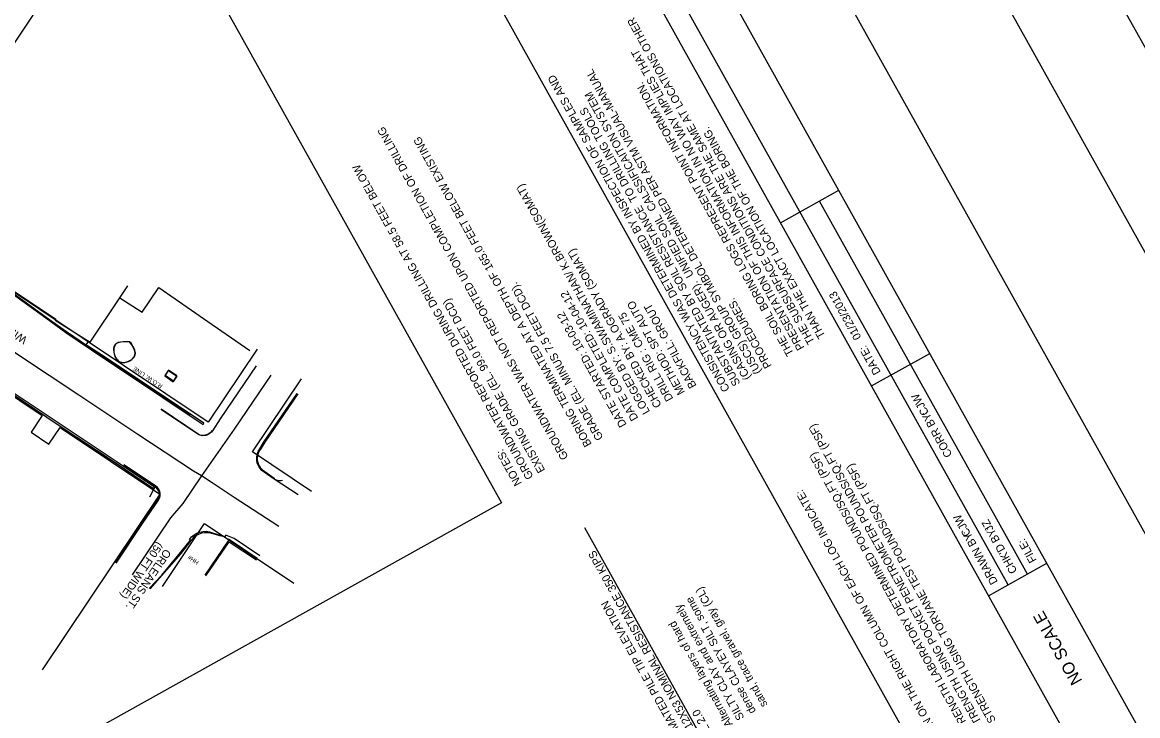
# Model space of a CAD drawing. Extents: x 13482447 to 13495412, y 324533 to 340229.
# Drawn here: x 13492545 to 13493214, y 331177 to 331592 of the extents above; entities that cross this region are included whole.
import ezdxf

# ---------------------------------------------------------------- set-up
doc = ezdxf.new("R2010")
doc.units = 0
for name, color, linetype in [('BORDER', 7, 'Continuous'), ('Default', 7, 'Continuous'), ('DETAIL_TEXT_DIMEN_PR', 7, 'Continuous'), ('Level 1', 7, 'Continuous'), ('TYPICAL_TEXT_DIMEN_PR', 7, 'Continuous'), ('V-ANNO-TEXT', 7, 'Continuous'), ('V-BLDG-OTLN', 7, 'Continuous'), ('V-PROP-RWAY', 7, 'Continuous'), ('V-PROP-RWAY-IDEN', 7, 'Continuous'), ('V-PVMT-BACK', 7, 'Continuous'), ('V-PVMT-CNTR', 7, 'Continuous'), ('V-PVMT-ROAD', 7, 'Continuous'), ('V-SITE-FENC-DEMO', 7, 'Continuous'), ('V-STRC-WALL', 7, 'Continuous'), ('V-TOPO-IDEN', 7, 'Continuous')]:
    doc.layers.add(name, color=color, linetype=linetype)

msp = doc.modelspace()

# ---------------------------------------------------------------- linework, layer by layer
at = {"layer": 'Default'}
for points in [[(13492586.34, 331745.09), (13492832.27, 331304.34)], [(13492832.27, 331304.34), (13492334.38, 331026.77)]]:
    msp.add_lwpolyline(points, dxfattribs=at)
at = {"layer": 'Level 1'}
for p, q in [((13493612.91, 330747.03), (13492913.2, 332001.03)), ((13493636.07, 330828.66), (13492994.84, 331977.87)), ((13493541.18, 330707.01), (13492841.48, 331961.01)), ((13493459.55, 330730.17), (13492818.32, 331879.38)), ((13493424.62, 330710.68), (13492783.39, 331859.89)), ((13493352.3, 330668.3), (13492709.75, 331819.87)), ((13493136.11, 331255.1), (13492824.27, 331813.99)), ((13492999.74, 331472.17), (13493034.69, 331491.66)), ((13493147.75, 331261.6), (13493023.02, 331485.15)), ((13493054.3, 331374.35), (13493089.23, 331393.84)), ((13493124.47, 331248.61), (13493159.4, 331268.1))]:
    msp.add_line(p, q, dxfattribs=at)
at = {"layer": 'TYPICAL_TEXT_DIMEN_PR'}
msp.add_line((13492981.96, 331110.55), (13492882.24, 331289.27), dxfattribs=at)
at = {"layer": 'V-BLDG-OTLN'}
for points in [[(13492472.33, 331479.25), (13492470.9, 331477.08), (13492480.41, 331470.94), (13492491.27, 331463.56), (13492512.34, 331449.48), (13492525.07, 331440.95), (13492565.12, 331414.41), (13492564.67, 331413.86), (13492585.61, 331400.62), (13492603.4, 331427.17), (13492608.29, 331434.36)], [(13492685.86, 331270.89), (13492668.78, 331282.18), (13492654.46, 331260.96)], [(13492655.05, 331260.55), (13492668.99, 331280.9), (13492685.37, 331270.16)]]:
    msp.add_lwpolyline(points, dxfattribs=at)
at = {"layer": 'V-PROP-RWAY'}
for p, q in [((13492570.67, 331625.86), (13492318.1, 331248.69)), ((13492656.37, 331352.6), (13492470.9, 331476.77)), ((13492461.91, 331420.21), (13492556.98, 331356.57)), ((13492685.74, 331396.48), (13492656.37, 331352.6)), ((13492682.96, 331334.8), (13492712.33, 331378.68)), ((13492556.98, 331356.57), (13492550.3, 331346.6)), ((13492560.94, 331339.48), (13492567.62, 331349.45)), ((13492567.62, 331349.45), (13492627.45, 331309.4)), ((13492550.3, 331346.6), (13492560.94, 331339.48)), ((13492718.45, 331311.05), (13492682.96, 331334.8)), ((13492627.45, 331309.4), (13492556.96, 331204.1)), ((13492628.98, 331254.17), (13492654.3, 331291.99)), ((13492654.3, 331291.99), (13492707.89, 331256.12))]:
    msp.add_line(p, q, dxfattribs=at)
at = {"layer": 'V-PVMT-BACK'}
for points in [[(13492710.13, 331369.7), (13492690.41, 331340.71), (13492688.14, 331337.09), (13492686.92, 331334.97), (13492686.45, 331333.96), (13492685.96, 331332.45), (13492685.76, 331330.92), (13492685.79, 331330.14), (13492685.96, 331329.08), (13492686.15, 331328.37), (13492686.7, 331327.02), (13492686.99, 331326.49), (13492687.65, 331325.5), (13492688.44, 331324.6), (13492689.04, 331324.04), (13492690.39, 331322.99), (13492696.09, 331319.02), (13492695.97, 331318.76)], [(13492601.13, 331268.22), (13492616.59, 331292.15), (13492620.02, 331297.42), (13492625.43, 331304.69), (13492626.37, 331306.1), (13492626.95, 331307.31), (13492627.22, 331308.62), (13492627.17, 331309.95), (13492626.81, 331311.24), (13492626.15, 331312.41), (13492625.24, 331313.39), (13492624.67, 331313.81)], [(13492621.56, 331307.91), (13492623.86, 331312.57), (13492624.67, 331313.81)], [(13492663.5, 331284.5), (13492662.88, 331284.67), (13492658.73, 331285.9), (13492658.01, 331286.1), (13492656.13, 331286.39), (13492654.23, 331286.36), (13492652.36, 331286.02), (13492650.57, 331285.37), (13492648.92, 331284.43), (13492647.45, 331283.22), (13492646.21, 331281.79), (13492646.15, 331281.71), (13492640.07, 331273.98), (13492621.45, 331252.64)]]:
    msp.add_lwpolyline(points, dxfattribs=at)
at = {"layer": 'V-PVMT-CNTR'}
for points in [[(13492698.81, 331290.16), (13492671.99, 331307.42), (13492658.91, 331316.29), (13492652.45, 331320.46), (13492647.72, 331323.27), (13492614.25, 331345.31), (13492578.94, 331368.92), (13492543.35, 331392.51), (13492508.4, 331416.01), (13492474.51, 331438.47), (13492456.22, 331451.24), (13492427.05, 331470.26), (13492400.48, 331488.1), (13492367.89, 331510.12), (13492333.56, 331533.05), (13492300.46, 331555.5), (13492272.59, 331574.14)], [(13492694.11, 331380.83), (13492672.13, 331348.5), (13492652.45, 331320.46), (13492641.24, 331303.81), (13492633.93, 331295.37), (13492610.86, 331261.17)]]:
    msp.add_lwpolyline(points, dxfattribs=at)
at = {"layer": 'V-PVMT-ROAD'}
for points in [[(13492603.4, 331427.17), (13492616.77, 331418.65), (13492626.79, 331433.32), (13492656.18, 331412.99), (13492681.52, 331395.55)], [(13492609.63, 331400.82), (13492606.72, 331400.89), (13492605.45, 331400.85), (13492603.78, 331400.68), (13492602.4, 331400.33), (13492601.81, 331400.08), (13492601.14, 331399.65), (13492600.85, 331399.39), (13492600.48, 331398.94), (13492600.07, 331398.13), (13492599.77, 331396.79), (13492599.72, 331396.13), (13492599.8, 331394.72), (13492599.99, 331393.64), (13492600.51, 331392.05), (13492600.86, 331391.31), (13492601.43, 331390.4), (13492601.76, 331389.99), (13492602.3, 331389.46), (13492603.22, 331388.84), (13492604.21, 331388.49), (13492604.92, 331388.38), (13492606.4, 331388.42), (13492607.16, 331388.55), (13492608.63, 331389.03), (13492609.56, 331389.47), (13492610.68, 331390.18), (13492611.17, 331390.58), (13492612.06, 331391.55), (13492612.49, 331392.32), (13492612.67, 331392.85), (13492612.79, 331393.98), (13492612.74, 331394.58), (13492612.42, 331395.86), (13492611.84, 331397.26), (13492611.32, 331398.28), (13492610.02, 331400.51)], [(13492609.48, 331400.75), (13492606.65, 331400.79), (13492605.42, 331400.75), (13492603.79, 331400.57), (13492602.44, 331400.22), (13492601.87, 331399.97), (13492601.22, 331399.55), (13492600.95, 331399.3), (13492600.59, 331398.86), (13492600.18, 331398.07), (13492599.89, 331396.73), (13492599.86, 331396.06), (13492599.95, 331394.65), (13492600.17, 331393.56), (13492600.71, 331391.98), (13492601.07, 331391.24), (13492601.66, 331390.34), (13492601.99, 331389.94), (13492602.55, 331389.41), (13492603.49, 331388.82), (13492604.45, 331388.52), (13492605.13, 331388.43), (13492606.55, 331388.51), (13492607.27, 331388.66), (13492608.68, 331389.15), (13492609.56, 331389.59), (13492610.62, 331390.3), (13492611.09, 331390.7), (13492611.93, 331391.64), (13492612.37, 331392.43), (13492612.55, 331392.98), (13492612.64, 331394.12), (13492612.57, 331394.73), (13492612.2, 331396.02), (13492611.56, 331397.43), (13492610.99, 331398.45), (13492609.56, 331400.7)], [(13492685.19, 331386.49), (13492663.66, 331354.56), (13492658.98, 331347.38), (13492658.38, 331346.63), (13492657.92, 331346.21), (13492656.9, 331345.52), (13492655.62, 331344.95), (13492654.95, 331344.74), (13492653.93, 331344.56), (13492652.84, 331344.54), (13492652.29, 331344.61), (13492651.49, 331344.82), (13492650.31, 331345.41), (13492628.12, 331360.25)], [(13492637.59, 331380.41), (13492632.67, 331383.83), (13492630.41, 331380.49), (13492635.43, 331376.91), (13492637.59, 331380.41)], [(13492635.57, 331377.18), (13492630.66, 331380.57), (13492632.65, 331383.57), (13492637.63, 331380.19), (13492635.57, 331377.18)], [(13492710.35, 331309.1), (13492695.99, 331318.51), (13492690.08, 331322.64), (13492688.68, 331323.7), (13492687.49, 331325), (13492686.56, 331326.49), (13492685.91, 331328.12), (13492685.57, 331329.85), (13492685.55, 331331.6), (13492685.85, 331333.33), (13492686.45, 331334.98), (13492686.79, 331335.63), (13492690.07, 331341.14), (13492709.84, 331369.81)], [(13492658.86, 331347.55), (13492658.03, 331346.6), (13492657.57, 331346.19), (13492656.8, 331345.68), (13492655.85, 331345.24), (13492655.35, 331345.06), (13492654.61, 331344.86), (13492653.73, 331344.7), (13492653.38, 331344.67), (13492652.65, 331344.69), (13492651.66, 331344.91), (13492651.16, 331345.1), (13492650.4, 331345.53), (13492628.2, 331360.37)], [(13492601.2, 331268.18), (13492617.04, 331291.85), (13492626.68, 331305.8), (13492627.32, 331307.06), (13492627.66, 331308.43), (13492627.68, 331309.85), (13492627.39, 331311.23), (13492626.79, 331312.51), (13492625.92, 331313.62), (13492624.91, 331314.46), (13492605.92, 331327.01)], [(13492624.34, 331314.11), (13492605.65, 331326.61)], [(13492624.34, 331314.11), (13492624.19, 331314.43), (13492605.83, 331326.87)], [(13492695.97, 331318.76), (13492697.26, 331318.11), (13492698.66, 331317.75), (13492700.1, 331317.7), (13492701.09, 331317.86)], [(13492621, 331252.88), (13492628.71, 331261.01), (13492639.78, 331274.43), (13492645.78, 331281.98), (13492645.21, 331282.4), (13492646.47, 331283.86), (13492647.96, 331285.09), (13492649.63, 331286.07), (13492651.43, 331286.75), (13492653.33, 331287.13), (13492655.26, 331287.2), (13492657.17, 331286.94), (13492658.46, 331286.58), (13492663.64, 331284.96)], [(13492687.42, 331272.6), (13492672.01, 331283), (13492667.07, 331284.85), (13492666.27, 331283.84), (13492663.5, 331284.5)], [(13492685.91, 331270.99), (13492668.69, 331282.51)]]:
    msp.add_lwpolyline(points, dxfattribs=at)
at = {"layer": 'V-SITE-FENC-DEMO'}
msp.add_lwpolyline([(13492645.79, 331356.95), (13492583.12, 331398.62), (13492584.65, 331400.92)], dxfattribs=at)
at = {"layer": 'V-STRC-WALL'}
for points in [[(13492480.33, 331470.68), (13492479.98, 331470.15), (13492484.13, 331467.24), (13492491.29, 331462.48), (13492511.4, 331449.18), (13492524.24, 331440.22), (13492559.05, 331415.13), (13492571.04, 331406.41), (13492593.96, 331391.09), (13492629.22, 331367.39), (13492653.43, 331351.28), (13492653.8, 331352.03), (13492594.32, 331391.77), (13492584.09, 331398.43)], [(13492480.33, 331470.68), (13492484.57, 331467.86), (13492491.31, 331463.36), (13492491.39, 331462.64), (13492511.49, 331449.32), (13492512.09, 331449.45), (13492524.62, 331440.7), (13492559.35, 331415.58), (13492571.41, 331406.94), (13492584.09, 331398.43)], [(13492623.75, 331312.67), (13492624.23, 331313.64), (13492601.21, 331328.99), (13492567.04, 331351.81), (13492531.63, 331375.4), (13492495.77, 331399.44), (13492461.16, 331422.5), (13492444.73, 331433.53), (13492444.47, 331433.7)], [(13492623.75, 331312.67), (13492600.59, 331328.22), (13492566.56, 331350.94), (13492531.02, 331374.67), (13492495.28, 331398.46), (13492460.47, 331421.69), (13492446.23, 331431.23)]]:
    msp.add_lwpolyline(points, dxfattribs=at)

# ---------------------------------------------------------------- texts
at = {"layer": 'BORDER'}
for s, p in [('THE SUBSURFACE CONDITIONS ARE THE SAME AT LOCATIONS OTHER ', (13493020.39, 331400.86)), ('PRESENTATION OF THIS INFORMATION IN NO WAY IMPLIES THAT ', (13493014.11, 331397.36)), ('(USCS) GROUP SYMBOL DETERMINED PER ASTM VISUAL-MANUAL ', (13492988.27, 331382.94)), ('CONSISTENCY WAS DETERMINED BY INSPECTION OF SAMPLES AND ', (13492969.41, 331372.42)), ('THE SOIL BORING LOGS REPRESENT POINT INFORMATION. ', (13493007.82, 331393.85)), ('(CASING OR AUGER).  UNIFIED SOIL  CALSSIFICAITON SYSTEM ', (13492981.99, 331379.43)), ('SUBSTANTIATED BY SOIL RESISTANCE  TO DRILLING TOOLS ', (13492975.7, 331375.92)), ('THAN THE EXACT LOCATION OF THE BORING.', (13493026.68, 331404.37)), ('PROCEDURES.', (13492994.56, 331386.45)), ('*PP  - UNCONFINED COMPRESSIVE STRENGTH USING POCKET PENETROMETER POUNDS/SQ.FT (PSF)', (13493176.92, 331071.54)), ('UCS - UNCONFINED COMPRESSIVE STRENGTH LABORATORY DETERMINED POUNDS/SQ.FT (PSF)', (13493169.93, 331067.64)), ('#TV  - UNCONFINED COMPRESSIVE STRENGTH USING TORVANE TEST POUNDS/SQ.FT (PSF)', (13493183.9, 331075.43)), ('LABORATORY AND FIELD TEST RESULTS SHOWN ON THE RIGHT COLUMN OF EACH LOG INDICATE:', (13493164.54, 331040.5))]:
    msp.add_text(s, height=4.8, rotation=119.16053, dxfattribs=at).set_placement(p)
at = {"layer": 'DETAIL_TEXT_DIMEN_PR'}
for s, p in [('GROUNDWATER WAS NOT REPORTED UPON COMPLETION OF DRILLING ', (13492872.61, 331331.64)), ('BORING TERMINATED AT A DEPTH OF 165.0 FEET BELOW EXISTING ', (13492886.58, 331339.43)), ('GROUNDWATER REPORTED DURING DRILLING AT 58.5 FEET BELOW', (13492851.65, 331319.94)), ('LOGGED BY: S.SWAMINATHAN/ K.BROWN(SOMAT)', (13492921.51, 331358.92)), ('CHECKED BY: A.OGRADY (SOMAT)', (13492928.5, 331362.82)), ('GRADE (EL. MINUS 7.5 FEET DCD).', (13492893.57, 331343.33)), ('DATE COMPLETED: 10-04-12', (13492914.52, 331355.03)), ('EXISTING GRADE (EL. 99.0 FEET DCD)', (13492858.64, 331323.84)), ('METHOD: SPT AUTO', (13492942.47, 331370.62)), ('BACKFILL: GROUT', (13492949.45, 331374.52)), ('DATE STARTED: 10-03-12', (13492907.54, 331351.13)), ('DRILL RIG : CME 75', (13492935.48, 331366.72)), ('NOTES:', (13492844.66, 331316.05)), ('HP 12X53 NOMINAL RESISTANCE 350 KIPS', (13492952.6, 331160.93)), ('sand, trace gravel, gray (CL)', (13492992.09, 331183.3)), ('ESTIMATED PILE TIP ELEVATION ', (13492945.62, 331157.03)), ('SILTY CLAY and extremely ', (13492978.11, 331175.5)), ('dense CLAYEY SILT, some ', (13492985.1, 331179.4)), ('Alternating layers of hard ', (13492971.13, 331171.61)), ('EL 2.0', (13492959.59, 331164.83))]:
    msp.add_text(s, height=4.8, rotation=119.16053, dxfattribs=at).set_placement(p)
at = {"layer": 'Level 1'}
for s, height, p in [('01/23/2013', 4.8, (13493048.24, 331403.55)), ('DATE:', 4.8, (13493059.91, 331382.64)), ('CJW               ', 4.8, (13493088.82, 331358.22)), ('CORR BY:', 4.8, (13493102.82, 331333.12)), ('CJW                                 ', 4.8, (13493114, 331285.73)), ('JZ                            ', 4.8, (13493127.63, 331288.65)), ("CHK'D BY:", 4.8, (13493141.73, 331263.4)), ('DRAWN BY:', 4.8, (13493130.08, 331256.9)), ('FILE:', 4.8, (13493153.37, 331269.89)), ('NO SCALE', 7.2, (13493180.8, 331197.57))]:
    msp.add_text(s, height=height, rotation=119.16053, dxfattribs=at).set_placement(p)
at = {"layer": 'V-ANNO-TEXT'}
for s, rotation, p in [('WILKINS ST.', 147.22098, (13492548.37, 331403.18)), ('(50 FT WIDE)', 235.78017, (13492625.8, 331281.33)), ('ORLEANS ST.', 235.78017, (13492630.6, 331277.04))]:
    msp.add_text(s, height=4.8, rotation=rotation, dxfattribs=at).set_placement(p)
at = {"layer": 'V-PROP-RWAY-IDEN'}
msp.add_text('R.O.W. LINE', height=2.56, rotation=146.19962, dxfattribs=at).set_placement((13492629.39, 331374.81))
at = {"layer": 'V-TOPO-IDEN'}
msp.add_text('HH#', height=2.56, rotation=145.04331, dxfattribs=at).set_placement((13492651.1, 331269.05))

doc.saveas('drawing.dxf')
